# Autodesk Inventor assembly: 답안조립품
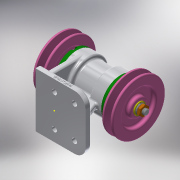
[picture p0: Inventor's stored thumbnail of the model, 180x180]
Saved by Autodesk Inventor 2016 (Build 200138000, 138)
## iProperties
Created: 2020-06
Part Number: 답안조립품
Material: 일반
Document SubType Name: Assembly
Designer: woori
Author: woori
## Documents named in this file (12)
- C:\Users\woori\Desktop\700606V1048\답안조립품.iam
- C:\Users\woori\Desktop\700606V1048\본체.ipt
- C:\Users\woori\Desktop\700606V1048\V-벨트풀리.ipt
- C:\Users\woori\Desktop\700606V1048\너트 M10.ipt
- C:\Users\woori\Desktop\700606V1048\베어링 6204.ipt
- C:\Users\woori\Desktop\700606V1048\볼트 M4.ipt
- C:\Users\woori\Desktop\700606V1048\스프링 와셔 10.ipt
- C:\Users\woori\Desktop\700606V1048\오일 실 20 32 5.ipt
- C:\Users\woori\Desktop\700606V1048\축.ipt
- C:\Users\woori\Desktop\700606V1048\커버.ipt
- C:\Users\woori\Desktop\700606V1048\키 5x5x12.ipt
- C:\Users\woori\Desktop\700606V1048\평면 와셔 10x21.ipt
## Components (2 placed, 1 different names)
1. V-벨트풀리:1
2. V-벨트풀리:2
